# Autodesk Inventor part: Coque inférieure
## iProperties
Created: 2010-07
Part Number: Coque inférieure
Document SubType Name: Modeling
Designer: eric
Density: 1 g/cm^3
Mass: 11.1191 g
Surface Area: 226.506 cm^2
Volume: 11.1191 cm^3
Author: eric
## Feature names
1. Hole1
2. Base1
